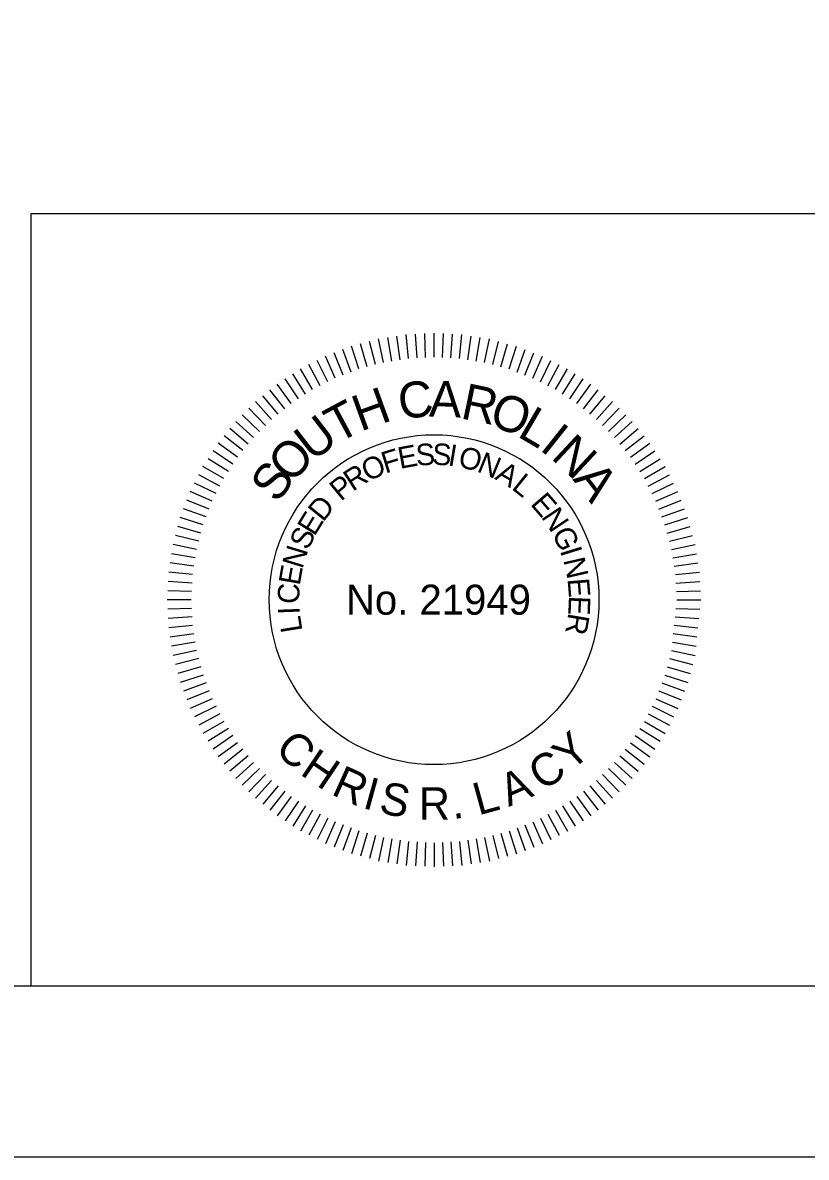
# Model space of a CAD drawing. Extents: x 1334.3 to 1370.4, y 717.9 to 739.9.
# Drawn here: x 1359.996 to 1362.28, y 717.865 to 721.171 of the extents above; entities that cross this region are included whole.
import ezdxf

# ---------------------------------------------------------------- set-up
doc = ezdxf.new("R2010")
doc.units = 0
for name, color, linetype in [('BR_BORDER LINES', 7, 'Continuous'), ('BR_DETAILS', 7, 'Continuous'), ('RD_SHT_IplotShp', 7, 'Continuous')]:
    doc.layers.add(name, color=color, linetype=linetype)

msp = doc.modelspace()

# ---------------------------------------------------------------- linework, layer by layer
at = {"layer": 'BR_BORDER LINES'}
for p, q in [((1360.0214, 720.6149), (1362.3339, 720.6149)), ((1360.0214, 718.3648), (1360.0214, 720.6149)), ((1336.1673, 718.3649), (1369.8339, 718.3649)), ((1334.334, 717.8663), (1370.334, 717.8663))]:
    msp.add_line(p, q, dxfattribs=at)
at = {"layer": 'BR_DETAILS'}
for p, q in [((1361.1705, 720.1953), (1361.1681, 720.2651)), ((1361.1705, 720.1953), (1361.1681, 720.2651)), ((1361.1952, 720.1966), (1361.1952, 720.2665)), ((1361.1952, 720.1966), (1361.1952, 720.2665)), ((1361.2199, 720.1953), (1361.2223, 720.2651)), ((1361.2199, 720.1953), (1361.2223, 720.2651)), ((1361.0004, 720.1684), (1360.9811, 720.2355)), ((1361.0004, 720.1684), (1360.9811, 720.2355)), ((1361.0242, 720.1748), (1361.0073, 720.2425)), ((1361.0242, 720.1748), (1361.0073, 720.2425)), ((1361.0481, 720.1812), (1361.0335, 720.2495)), ((1361.0481, 720.1812), (1361.0335, 720.2495)), ((1361.0725, 720.185), (1361.0603, 720.2538)), ((1361.0725, 720.185), (1361.0603, 720.2538)), ((1361.0968, 720.1889), (1361.0871, 720.258)), ((1361.0968, 720.1889), (1361.0871, 720.258)), ((1361.1212, 720.1928), (1361.1139, 720.2623)), ((1361.1212, 720.1928), (1361.1139, 720.2623)), ((1361.1459, 720.194), (1361.141, 720.2637)), ((1361.1459, 720.194), (1361.141, 720.2637)), ((1361.2445, 720.194), (1361.2494, 720.2637)), ((1361.2445, 720.194), (1361.2494, 720.2637)), ((1361.2692, 720.1928), (1361.2765, 720.2623)), ((1361.2692, 720.1928), (1361.2765, 720.2623)), ((1361.2936, 720.1889), (1361.3033, 720.258)), ((1361.2936, 720.1889), (1361.3033, 720.258)), ((1361.318, 720.185), (1361.3301, 720.2538)), ((1361.318, 720.185), (1361.3301, 720.2538)), ((1361.3424, 720.1812), (1361.3569, 720.2495)), ((1361.3424, 720.1812), (1361.3569, 720.2495)), ((1361.3424, 720.1812), (1361.3569, 720.2495)), ((1361.3662, 720.1748), (1361.3831, 720.2425)), ((1361.3662, 720.1748), (1361.3831, 720.2425)), ((1361.3662, 720.1748), (1361.3831, 720.2425)), ((1361.39, 720.1684), (1361.4093, 720.2355)), ((1361.39, 720.1684), (1361.4093, 720.2355)), ((1361.39, 720.1684), (1361.4093, 720.2355)), ((1360.9074, 720.1354), (1360.8789, 720.1993)), ((1360.9074, 720.1354), (1360.8789, 720.1993)), ((1360.9304, 720.1443), (1360.9043, 720.209)), ((1360.9304, 720.1443), (1360.9043, 720.209)), ((1360.9535, 720.1531), (1360.9296, 720.2187)), ((1360.9535, 720.1531), (1360.9296, 720.2187)), ((1360.9765, 720.162), (1360.9549, 720.2285)), ((1360.9765, 720.162), (1360.9549, 720.2285)), ((1361.4139, 720.162), (1361.4355, 720.2285)), ((1361.4139, 720.162), (1361.4355, 720.2285)), ((1361.4139, 720.162), (1361.4355, 720.2285)), ((1361.437, 720.1531), (1361.4608, 720.2187)), ((1361.437, 720.1531), (1361.4608, 720.2187)), ((1361.437, 720.1531), (1361.4608, 720.2187)), ((1361.46, 720.1443), (1361.4862, 720.209)), ((1361.46, 720.1443), (1361.4862, 720.209)), ((1361.46, 720.1443), (1361.4862, 720.209)), ((1361.4831, 720.1354), (1361.5115, 720.1993)), ((1361.4831, 720.1354), (1361.5115, 720.1993)), ((1361.4831, 720.1354), (1361.5115, 720.1993)), ((1360.8634, 720.113), (1360.8306, 720.1747)), ((1360.8634, 720.113), (1360.8306, 720.1747)), ((1360.8854, 720.1242), (1360.8548, 720.187)), ((1360.8854, 720.1242), (1360.8548, 720.187)), ((1361.5051, 720.1242), (1361.5357, 720.187)), ((1361.5051, 720.1242), (1361.5357, 720.187)), ((1361.5051, 720.1242), (1361.5357, 720.187)), ((1361.5271, 720.113), (1361.5598, 720.1747)), ((1361.5271, 720.113), (1361.5598, 720.1747)), ((1361.5271, 720.113), (1361.5598, 720.1747)), ((1360.8, 720.0749), (1360.7609, 720.1328)), ((1360.8, 720.0749), (1360.7609, 720.1328)), ((1360.8206, 720.0884), (1360.7836, 720.1476)), ((1360.8206, 720.0884), (1360.7836, 720.1476)), ((1360.8414, 720.1018), (1360.8064, 720.1624)), ((1360.8414, 720.1018), (1360.8064, 720.1624)), ((1361.5491, 720.1018), (1361.584, 720.1624)), ((1361.5491, 720.1018), (1361.584, 720.1624)), ((1361.5491, 720.1018), (1361.584, 720.1624)), ((1361.5698, 720.0884), (1361.6068, 720.1476)), ((1361.5698, 720.0884), (1361.6068, 720.1476)), ((1361.5698, 720.0884), (1361.6068, 720.1476)), ((1361.5905, 720.0749), (1361.6295, 720.1328)), ((1361.5905, 720.0749), (1361.6295, 720.1328)), ((1361.5905, 720.0749), (1361.6295, 720.1328)), ((1360.76, 720.0459), (1360.7171, 720.1009)), ((1360.76, 720.0459), (1360.7171, 720.1009)), ((1360.7792, 720.0615), (1360.7382, 720.118)), ((1360.7792, 720.0615), (1360.7382, 720.118)), ((1361.6112, 720.0615), (1361.6523, 720.118)), ((1361.6112, 720.0615), (1361.6523, 720.118)), ((1361.6112, 720.0615), (1361.6523, 720.118)), ((1361.6304, 720.0459), (1361.6734, 720.1009)), ((1361.6304, 720.0459), (1361.6734, 720.1009)), ((1361.6304, 720.0459), (1361.6734, 720.1009)), ((1360.7217, 720.0149), (1360.6749, 720.0668)), ((1360.7217, 720.0149), (1360.6749, 720.0668)), ((1360.7409, 720.0304), (1360.696, 720.0839)), ((1360.7409, 720.0304), (1360.696, 720.0839)), ((1361.6496, 720.0304), (1361.6944, 720.0839)), ((1361.6496, 720.0304), (1361.6944, 720.0839)), ((1361.6496, 720.0304), (1361.6944, 720.0839)), ((1361.6688, 720.0149), (1361.7155, 720.0668)), ((1361.6688, 720.0149), (1361.7155, 720.0668)), ((1361.6688, 720.0149), (1361.7155, 720.0668)), ((1360.7042, 719.9974), (1360.6557, 720.0476)), ((1360.7042, 719.9974), (1360.6557, 720.0476)), ((1361.6862, 719.9974), (1361.7347, 720.0476)), ((1361.6862, 719.9974), (1361.7347, 720.0476)), ((1361.6862, 719.9974), (1361.7347, 720.0476)), ((1360.6693, 719.9625), (1360.6173, 720.0092)), ((1360.6693, 719.9625), (1360.6173, 720.0092)), ((1360.6868, 719.9799), (1360.6365, 720.0284)), ((1360.6868, 719.9799), (1360.6365, 720.0284)), ((1361.7037, 719.9799), (1361.7539, 720.0284)), ((1361.7037, 719.9799), (1361.7539, 720.0284)), ((1361.7037, 719.9799), (1361.7539, 720.0284)), ((1361.7211, 719.9625), (1361.7731, 720.0092)), ((1361.7211, 719.9625), (1361.7731, 720.0092)), ((1361.7211, 719.9625), (1361.7731, 720.0092)), ((1360.6382, 719.9241), (1360.5832, 719.9671)), ((1360.6382, 719.9241), (1360.5832, 719.9671)), ((1360.6537, 719.9433), (1360.6003, 719.9882)), ((1360.6537, 719.9433), (1360.6003, 719.9882)), ((1361.7367, 719.9433), (1361.7902, 719.9882)), ((1361.7367, 719.9433), (1361.7902, 719.9882)), ((1361.7367, 719.9433), (1361.7902, 719.9882)), ((1361.7522, 719.9241), (1361.8072, 719.9671)), ((1361.7522, 719.9241), (1361.8072, 719.9671)), ((1361.7522, 719.9241), (1361.8072, 719.9671)), ((1360.6227, 719.9049), (1360.5661, 719.946)), ((1360.6227, 719.9049), (1360.5661, 719.946)), ((1361.7678, 719.9049), (1361.8243, 719.946)), ((1361.7678, 719.9049), (1361.8243, 719.946)), ((1361.7678, 719.9049), (1361.8243, 719.946)), ((1360.5958, 719.8635), (1360.5366, 719.9005)), ((1360.5958, 719.8635), (1360.5366, 719.9005)), ((1360.6092, 719.8842), (1360.5513, 719.9232)), ((1360.6092, 719.8842), (1360.5513, 719.9232)), ((1361.7812, 719.8842), (1361.8391, 719.9232)), ((1361.7812, 719.8842), (1361.8391, 719.9232)), ((1361.7812, 719.8842), (1361.8391, 719.9232)), ((1361.7946, 719.8635), (1361.8539, 719.9005)), ((1361.7946, 719.8635), (1361.8539, 719.9005)), ((1361.7946, 719.8635), (1361.8539, 719.9005)), ((1360.5823, 719.8428), (1360.5218, 719.8777)), ((1360.5823, 719.8428), (1360.5218, 719.8777)), ((1361.8081, 719.8428), (1361.8686, 719.8777)), ((1361.8081, 719.8428), (1361.8686, 719.8777)), ((1361.8081, 719.8428), (1361.8686, 719.8777)), ((1360.5711, 719.8208), (1360.5095, 719.8535)), ((1360.5711, 719.8208), (1360.5095, 719.8535)), ((1361.8193, 719.8208), (1361.881, 719.8535)), ((1361.8193, 719.8208), (1361.881, 719.8535)), ((1361.8193, 719.8208), (1361.881, 719.8535)), ((1360.5487, 719.7768), (1360.4848, 719.8052)), ((1360.5487, 719.7768), (1360.4848, 719.8052)), ((1360.5599, 719.7988), (1360.4972, 719.8294)), ((1360.5599, 719.7988), (1360.4972, 719.8294)), ((1361.8305, 719.7988), (1361.8933, 719.8294)), ((1361.8305, 719.7988), (1361.8933, 719.8294)), ((1361.8305, 719.7988), (1361.8933, 719.8294)), ((1361.8417, 719.7768), (1361.9056, 719.8052)), ((1361.8417, 719.7768), (1361.9056, 719.8052)), ((1361.8417, 719.7768), (1361.9056, 719.8052)), ((1360.5398, 719.7537), (1360.4751, 719.7799)), ((1360.5398, 719.7537), (1360.4751, 719.7799)), ((1361.8506, 719.7537), (1361.9153, 719.7799)), ((1361.8506, 719.7537), (1361.9153, 719.7799)), ((1361.8506, 719.7537), (1361.9153, 719.7799)), ((1360.531, 719.7307), (1360.4654, 719.7546)), ((1360.531, 719.7307), (1360.4654, 719.7546)), ((1361.8594, 719.7307), (1361.925, 719.7546)), ((1361.8594, 719.7307), (1361.925, 719.7546)), ((1361.8594, 719.7307), (1361.925, 719.7546)), ((1360.5158, 719.6838), (1360.4486, 719.703)), ((1360.5158, 719.6838), (1360.4486, 719.703)), ((1360.5221, 719.7076), (1360.4557, 719.7292)), ((1360.5221, 719.7076), (1360.4557, 719.7292)), ((1361.8683, 719.7076), (1361.9348, 719.7292)), ((1361.8683, 719.7076), (1361.9348, 719.7292)), ((1361.8683, 719.7076), (1361.9348, 719.7292)), ((1361.8747, 719.6838), (1361.9418, 719.703)), ((1361.8747, 719.6838), (1361.9418, 719.703)), ((1361.8747, 719.6838), (1361.9418, 719.703)), ((1360.5094, 719.6599), (1360.4416, 719.6768)), ((1360.5094, 719.6599), (1360.4416, 719.6768)), ((1361.8811, 719.6599), (1361.9488, 719.6768)), ((1361.8811, 719.6599), (1361.9488, 719.6768)), ((1361.8811, 719.6599), (1361.9488, 719.6768)), ((1360.503, 719.6361), (1360.4346, 719.6506)), ((1360.503, 719.6361), (1360.4346, 719.6506)), ((1361.8875, 719.6361), (1361.9558, 719.6506)), ((1361.8875, 719.6361), (1361.9558, 719.6506)), ((1361.8875, 719.6361), (1361.9558, 719.6506)), ((1360.4991, 719.6117), (1360.4304, 719.6238)), ((1360.4991, 719.6117), (1360.4304, 719.6238)), ((1361.8913, 719.6117), (1361.9601, 719.6238)), ((1361.8913, 719.6117), (1361.9601, 719.6238)), ((1361.8913, 719.6117), (1361.9601, 719.6238)), ((1360.4914, 719.5629), (1360.4219, 719.5702)), ((1360.4914, 719.5629), (1360.4219, 719.5702)), ((1360.4953, 719.5873), (1360.4261, 719.597)), ((1360.4953, 719.5873), (1360.4261, 719.597)), ((1361.8952, 719.5873), (1361.9643, 719.597)), ((1361.8952, 719.5873), (1361.9643, 719.597)), ((1361.8952, 719.5873), (1361.9643, 719.597)), ((1361.899, 719.5629), (1361.9686, 719.5702)), ((1361.899, 719.5629), (1361.9686, 719.5702)), ((1361.899, 719.5629), (1361.9686, 719.5702)), ((1360.4901, 719.5382), (1360.4205, 719.5431)), ((1360.4901, 719.5382), (1360.4205, 719.5431)), ((1361.9003, 719.5382), (1361.97, 719.5431)), ((1361.9003, 719.5382), (1361.97, 719.5431)), ((1361.9003, 719.5382), (1361.97, 719.5431)), ((1360.4888, 719.5136), (1360.419, 719.516)), ((1360.4888, 719.5136), (1360.419, 719.516)), ((1361.9016, 719.5136), (1361.9714, 719.516)), ((1361.9016, 719.5136), (1361.9714, 719.516)), ((1361.9016, 719.5136), (1361.9714, 719.516)), ((1360.4875, 719.4889), (1360.4176, 719.4889)), ((1360.4875, 719.4889), (1360.4176, 719.4889)), ((1361.9029, 719.4889), (1361.9728, 719.4889)), ((1361.9029, 719.4889), (1361.9728, 719.4889)), ((1361.9029, 719.4889), (1361.9728, 719.4889)), ((1360.4888, 719.4643), (1360.419, 719.4618)), ((1360.4888, 719.4643), (1360.419, 719.4618)), ((1360.4901, 719.4396), (1360.4205, 719.4348)), ((1360.4901, 719.4396), (1360.4205, 719.4348)), ((1361.8978, 719.4398), (1361.9671, 719.435)), ((1361.8978, 719.4398), (1361.9671, 719.435)), ((1361.9003, 719.4643), (1361.97, 719.4619)), ((1361.9003, 719.4643), (1361.97, 719.4619)), ((1360.4914, 719.415), (1360.4219, 719.4076)), ((1360.4914, 719.415), (1360.4219, 719.4076)), ((1361.8952, 719.4154), (1361.9643, 719.4081)), ((1361.8952, 719.4154), (1361.9643, 719.4081)), ((1360.4953, 719.3906), (1360.4261, 719.3808)), ((1360.4953, 719.3906), (1360.4261, 719.3808)), ((1361.8926, 719.3909), (1361.9615, 719.3812)), ((1361.8926, 719.3909), (1361.9615, 719.3812)), ((1360.4991, 719.3662), (1360.4304, 719.3541)), ((1360.4991, 719.3662), (1360.4304, 719.3541)), ((1360.503, 719.3418), (1360.4346, 719.3273)), ((1360.503, 719.3418), (1360.4346, 719.3273)), ((1361.8875, 719.3418), (1361.9558, 719.3273)), ((1361.8875, 719.3418), (1361.9558, 719.3273)), ((1361.89, 719.3664), (1361.9587, 719.3543)), ((1361.89, 719.3664), (1361.9587, 719.3543)), ((1360.5094, 719.3179), (1360.4416, 719.301)), ((1360.5094, 719.3179), (1360.4416, 719.301)), ((1361.8811, 719.3179), (1361.9488, 719.301)), ((1361.8811, 719.3179), (1361.9488, 719.301)), ((1360.5158, 719.2941), (1360.4486, 719.2749)), ((1360.5158, 719.2941), (1360.4486, 719.2749)), ((1361.8747, 719.2941), (1361.9418, 719.2749)), ((1361.8747, 719.2941), (1361.9418, 719.2749)), ((1360.5221, 719.2702), (1360.4557, 719.2486)), ((1360.531, 719.2472), (1360.4654, 719.2233)), ((1360.531, 719.2472), (1360.4654, 719.2233)), ((1361.8594, 719.2472), (1361.925, 719.2233)), ((1361.8594, 719.2472), (1361.925, 719.2233)), ((1361.8683, 719.2702), (1361.9348, 719.2486)), ((1361.8683, 719.2702), (1361.9348, 719.2486)), ((1360.5398, 719.2241), (1360.4751, 719.198)), ((1360.5398, 719.2241), (1360.4751, 719.198)), ((1361.8506, 719.2241), (1361.9153, 719.198)), ((1361.8506, 719.2241), (1361.9153, 719.198)), ((1360.5487, 719.2011), (1360.4848, 719.1727)), ((1360.5487, 719.2011), (1360.4848, 719.1727)), ((1360.5599, 719.1791), (1360.4972, 719.1485)), ((1360.5599, 719.1791), (1360.4972, 719.1485)), ((1361.8305, 719.1791), (1361.8933, 719.1485)), ((1361.8305, 719.1791), (1361.8933, 719.1485)), ((1361.8417, 719.2011), (1361.9056, 719.1727)), ((1361.8417, 719.2011), (1361.9056, 719.1727)), ((1360.5711, 719.1571), (1360.5095, 719.1243)), ((1360.5711, 719.1571), (1360.5095, 719.1243)), ((1361.8193, 719.1571), (1361.881, 719.1243)), ((1361.8193, 719.1571), (1361.881, 719.1243)), ((1360.5823, 719.1351), (1360.5218, 719.1001)), ((1360.5823, 719.1351), (1360.5218, 719.1001)), ((1360.5958, 719.1144), (1360.5366, 719.0774)), ((1360.5958, 719.1144), (1360.5366, 719.0774)), ((1361.7946, 719.1144), (1361.8539, 719.0774)), ((1361.7946, 719.1144), (1361.8539, 719.0774)), ((1361.8081, 719.1351), (1361.8686, 719.1001)), ((1361.8081, 719.1351), (1361.8686, 719.1001)), ((1360.6092, 719.0937), (1360.5513, 719.0546)), ((1360.6092, 719.0937), (1360.5513, 719.0546)), ((1361.7812, 719.0937), (1361.8391, 719.0546)), ((1361.7812, 719.0937), (1361.8391, 719.0546)), ((1360.6227, 719.073), (1360.5661, 719.0319)), ((1360.6227, 719.073), (1360.5661, 719.0319)), ((1360.6382, 719.0538), (1360.5832, 719.0108)), ((1360.6382, 719.0538), (1360.5832, 719.0108)), ((1361.7522, 719.0538), (1361.8072, 719.0108)), ((1361.7522, 719.0538), (1361.8072, 719.0108)), ((1361.7678, 719.073), (1361.8243, 719.0319)), ((1361.7678, 719.073), (1361.8243, 719.0319)), ((1360.6537, 719.0346), (1360.6003, 718.9897)), ((1360.6537, 719.0346), (1360.6003, 718.9897)), ((1360.6693, 719.0154), (1360.6173, 718.9686)), ((1360.6693, 719.0154), (1360.6173, 718.9686)), ((1361.7211, 719.0154), (1361.7731, 718.9686)), ((1361.7211, 719.0154), (1361.7731, 718.9686)), ((1361.7367, 719.0346), (1361.7902, 718.9897)), ((1361.7367, 719.0346), (1361.7902, 718.9897)), ((1360.6868, 718.9979), (1360.6365, 718.9494)), ((1360.6868, 718.9979), (1360.6365, 718.9494)), ((1360.7042, 718.9805), (1360.6557, 718.9303)), ((1360.7042, 718.9805), (1360.6557, 718.9303)), ((1361.6862, 718.9805), (1361.7347, 718.9303)), ((1361.6862, 718.9805), (1361.7347, 718.9303)), ((1361.7037, 718.9979), (1361.7539, 718.9494)), ((1361.7037, 718.9979), (1361.7539, 718.9494)), ((1360.7217, 718.963), (1360.6749, 718.9111)), ((1360.7217, 718.963), (1360.6749, 718.9111)), ((1360.7409, 718.9475), (1360.696, 718.894)), ((1360.7409, 718.9475), (1360.696, 718.894)), ((1361.6496, 718.9475), (1361.6944, 718.894)), ((1361.6496, 718.9475), (1361.6944, 718.894)), ((1361.6688, 718.963), (1361.7155, 718.9111)), ((1360.76, 718.9319), (1360.7171, 718.8769)), ((1360.76, 718.9319), (1360.7171, 718.8769)), ((1360.7792, 718.9164), (1360.7382, 718.8598)), ((1360.7792, 718.9164), (1360.7382, 718.8598)), ((1361.6112, 718.9164), (1361.6523, 718.8598)), ((1361.6112, 718.9164), (1361.6523, 718.8598)), ((1361.6304, 718.9319), (1361.6734, 718.8769)), ((1361.6304, 718.9319), (1361.6734, 718.8769)), ((1360.8, 718.9029), (1360.7609, 718.8451)), ((1360.8, 718.9029), (1360.7609, 718.8451)), ((1360.8206, 718.8895), (1360.7836, 718.8303)), ((1360.8206, 718.8895), (1360.7836, 718.8303)), ((1360.8414, 718.876), (1360.8064, 718.8155)), ((1360.8414, 718.876), (1360.8064, 718.8155)), ((1361.5491, 718.876), (1361.584, 718.8155)), ((1361.5491, 718.876), (1361.584, 718.8155)), ((1361.5698, 718.8895), (1361.6068, 718.8303)), ((1361.5698, 718.8895), (1361.6068, 718.8303)), ((1361.5905, 718.9029), (1361.6295, 718.8451)), ((1361.5905, 718.9029), (1361.6295, 718.8451)), ((1360.8634, 718.8648), (1360.8306, 718.8032)), ((1360.8634, 718.8648), (1360.8306, 718.8032)), ((1360.8854, 718.8536), (1360.8548, 718.7909)), ((1360.8854, 718.8536), (1360.8548, 718.7909)), ((1360.9074, 718.8424), (1360.8789, 718.7786)), ((1360.9074, 718.8424), (1360.8789, 718.7786)), ((1361.4831, 718.8424), (1361.5115, 718.7786)), ((1361.4831, 718.8424), (1361.5115, 718.7786)), ((1361.5051, 718.8536), (1361.5357, 718.7909)), ((1361.5051, 718.8536), (1361.5357, 718.7909)), ((1361.5271, 718.8648), (1361.5598, 718.8032)), ((1361.5271, 718.8648), (1361.5598, 718.8032)), ((1360.9304, 718.8336), (1360.9043, 718.7688)), ((1360.9304, 718.8336), (1360.9043, 718.7688)), ((1360.9535, 718.8247), (1360.9296, 718.7591)), ((1360.9535, 718.8247), (1360.9296, 718.7591)), ((1360.9765, 718.8159), (1360.9549, 718.7494)), ((1360.9765, 718.8159), (1360.9549, 718.7494)), ((1361.0004, 718.8095), (1360.9811, 718.7424)), ((1361.0004, 718.8095), (1360.9811, 718.7424)), ((1361.39, 718.8095), (1361.4093, 718.7424)), ((1361.39, 718.8095), (1361.4093, 718.7424)), ((1361.4139, 718.8159), (1361.4355, 718.7494)), ((1361.4139, 718.8159), (1361.4355, 718.7494)), ((1361.437, 718.8247), (1361.4608, 718.7591)), ((1361.437, 718.8247), (1361.4608, 718.7591)), ((1361.46, 718.8336), (1361.4862, 718.7688)), ((1361.46, 718.8336), (1361.4862, 718.7688)), ((1361.0242, 718.8031), (1361.0073, 718.7353)), ((1361.0242, 718.8031), (1361.0073, 718.7353)), ((1361.0481, 718.7967), (1361.0335, 718.7283)), ((1361.0481, 718.7967), (1361.0335, 718.7283)), ((1361.0725, 718.7928), (1361.0603, 718.7241)), ((1361.0725, 718.7928), (1361.0603, 718.7241)), ((1361.0968, 718.789), (1361.0871, 718.7198)), ((1361.0968, 718.789), (1361.0871, 718.7198)), ((1361.1212, 718.7851), (1361.1139, 718.7156)), ((1361.1212, 718.7851), (1361.1139, 718.7156)), ((1361.1459, 718.7838), (1361.141, 718.7142)), ((1361.1459, 718.7838), (1361.141, 718.7142)), ((1361.1705, 718.7825), (1361.1681, 718.7128)), ((1361.1705, 718.7825), (1361.1681, 718.7128)), ((1361.1952, 718.7812), (1361.1952, 718.7113)), ((1361.1952, 718.7812), (1361.1952, 718.7113)), ((1361.2199, 718.7825), (1361.2223, 718.7128)), ((1361.2199, 718.7825), (1361.2223, 718.7128)), ((1361.2445, 718.7838), (1361.2494, 718.7142)), ((1361.2445, 718.7838), (1361.2494, 718.7142)), ((1361.2692, 718.7851), (1361.2765, 718.7156)), ((1361.2692, 718.7851), (1361.2765, 718.7156)), ((1361.2936, 718.789), (1361.3033, 718.7198)), ((1361.2936, 718.789), (1361.3033, 718.7198)), ((1361.318, 718.7928), (1361.3301, 718.7241)), ((1361.318, 718.7928), (1361.3301, 718.7241)), ((1361.3424, 718.7967), (1361.3569, 718.7283)), ((1361.3424, 718.7967), (1361.3569, 718.7283)), ((1361.3662, 718.8031), (1361.3831, 718.7353)), ((1361.3662, 718.8031), (1361.3831, 718.7353))]:
    msp.add_line(p, q, dxfattribs=at)
msp.add_circle((1361.1952, 719.4898), 0.4805, dxfattribs=at)
at = {"layer": 'RD_SHT_IplotShp'}
msp.add_lwpolyline([(1334.334, 739.8649), (1370.334, 739.8649), (1370.334, 717.8649), (1334.334, 717.8649)], close=True, dxfattribs=at)

# ---------------------------------------------------------------- texts
at = {"layer": 'BR_DETAILS'}
for s, height, rotation, p in [('H', 0.1048, 19.9102, (1360.9811, 719.9791)), ('C', 0.1048, 6.8832, (1361.0969, 720.0148)), ('A', 0.1048, 357.9448, (1361.1797, 720.0237)), ('R', 0.1048, 348.267, (1361.2697, 720.0187)), ('T', 0.1048, 28.0947, (1360.9136, 719.9437)), ('O', 0.1048, 339.3286, (1361.3509, 720.0007)), ('L', 0.1048, 329.6507, (1361.4346, 719.9673)), ('U', 0.1048, 37.7726, (1360.8414, 719.8899)), ('I', 0.1048, 321.4663, (1361.5001, 719.9283)), ('N', 0.1048, 317.0007, (1361.5333, 719.9032)), ('O', 0.1048, 47.4504, (1360.7791, 719.8247)), ('E', 0.0628, 10.5018, (1361.0959, 719.8707)), ('S', 0.0628, 3.4002, (1361.1438, 719.88)), ('S', 0.0628, 356.8566, (1361.1886, 719.8833)), ('I', 0.0628, 350.313, (1361.2334, 719.8815)), ('O', 0.0628, 346.0455, (1361.2625, 719.8776)), ('O', 0.0628, 25.285, (1361.002, 719.8327)), ('F', 0.0628, 17.0454, (1361.0532, 719.8569)), ('N', 0.0628, 337.8059, (1361.3174, 719.864)), ('S', 0.1048, 54.9027, (1360.7392, 719.7679)), ('R', 0.0628, 32.9611, (1360.9579, 719.8038)), ('A', 0.0628, 329.5663, (1361.3697, 719.8426)), ('A', 0.1048, 307.3229, (1361.598, 719.8405)), ('P', 0.0628, 39.5047, (1360.9237, 719.7748)), ('L', 0.0628, 321.3267, (1361.4185, 719.8139)), ('E', 0.0628, 310.8083, (1361.4739, 719.7677)), ('D', 0.0628, 51.1611, (1360.8717, 719.714)), ('E', 0.0628, 58.2627, (1360.8465, 719.6723)), ('N', 0.0628, 303.7068, (1361.5061, 719.7312)), ('S', 0.0628, 64.8063, (1360.828, 719.6314)), ('G', 0.0628, 295.4672, (1361.5375, 719.6841)), ('N', 0.0628, 73.0458, (1360.8115, 719.5773)), ('I', 0.0628, 287.2276, (1361.5618, 719.633)), ('N', 0.0628, 282.96, (1361.5715, 719.6054)), ('E', 0.0628, 80.1474, (1360.8036, 719.5292)), ('E', 0.0628, 274.7205, (1361.5841, 719.5502)), ('C', 0.0628, 87.8235, (1360.8018, 719.4765)), ('E', 0.0628, 267.6189, (1361.5886, 719.5017)), ('I', 0.0628, 92.0911, (1360.8039, 719.4473)), ('L', 0.0628, 99.1926, (1360.8122, 719.3992)), ('R', 0.0628, 260.5173, (1361.5871, 719.453)), ('Y', 0.0942, 42.1707, (1361.5938, 718.9864)), ('C', 0.0942, 317.0914, (1360.7278, 719.0495)), ('H', 0.0942, 326.011, (1360.8017, 718.9823)), ('C', 0.0942, 33.2512, (1361.511, 718.9306)), ('R', 0.0942, 335.6684, (1360.8925, 718.9235)), ('A', 0.0942, 23.5938, (1361.4127, 718.8856)), ('I', 0.0942, 344.5879, (1360.9839, 718.8834)), ('S', 0.0942, 349.0441, (1361.0317, 718.8688)), ('R', 0.0942, 359.8228, (1361.1507, 718.8492)), ('L', 0.0942, 15.4265, (1361.3246, 718.8608)), ('.', 0.0942, 8.7423, (1361.2506, 718.85))]:
    msp.add_text(s, height=height, rotation=rotation, dxfattribs=at).set_placement(p)
msp.add_text('No. 21949', height=0.08737, dxfattribs=at).set_placement((1360.9385, 719.4461))

doc.saveas('drawing.dxf')
